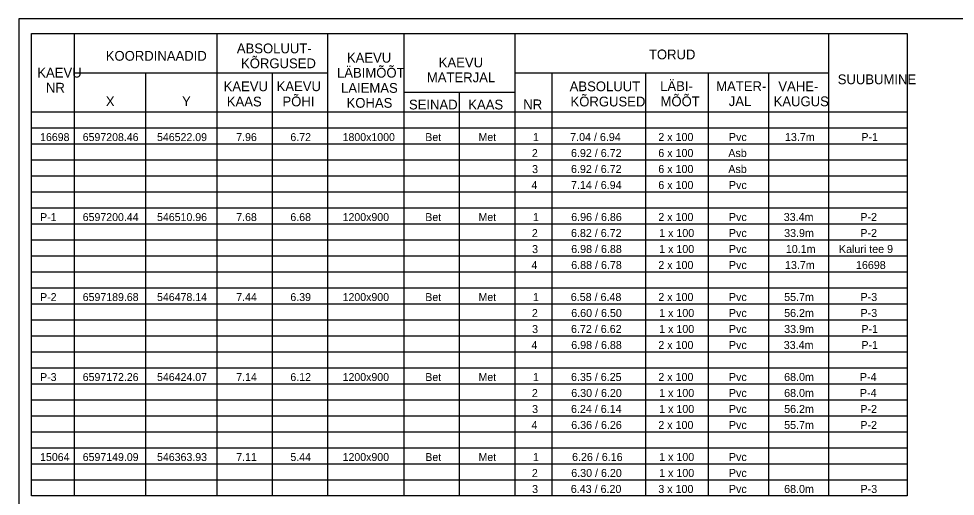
# Model space of a CAD drawing. Extents: x 546339 to 546593, y 6597108 to 6597251.
# Drawn here: x 546339.4 to 546434.2, y 6597202.4 to 6597250.7 of the extents above; entities that cross this region are included whole.
import ezdxf

# ---------------------------------------------------------------- set-up
doc = ezdxf.new("R2010")
doc.units = 0
doc.layers.add('ABIJOONIS', color=7, linetype='Continuous')
doc.layers.add('VORMISTUS', color=7, linetype='Continuous')

msp = doc.modelspace()

# ---------------------------------------------------------------- linework, layer by layer
at = {"layer": 'ABIJOONIS'}
msp.add_lwpolyline([(546340.681, 6597249.216), (546429.304, 6597249.216), (546429.304, 6597202.416), (546340.681, 6597202.416)], close=True, dxfattribs=at)
for points in [[(546344.997, 6597249.216), (546344.997, 6597202.416)], [(546359.423, 6597249.216), (546359.423, 6597202.416)], [(546370.643, 6597249.216), (546370.643, 6597202.416)], [(546378.364, 6597249.216), (546378.364, 6597202.416)], [(546389.584, 6597249.216), (546389.584, 6597202.416)], [(546421.342, 6597249.216), (546421.342, 6597202.416)], [(546344.997, 6597245.256), (546370.643, 6597245.256)], [(546352.21, 6597245.256), (546352.21, 6597202.416)], [(546365.033, 6597245.256), (546365.033, 6597202.416)], [(546389.584, 6597245.256), (546421.342, 6597245.256)], [(546393.324, 6597245.256), (546393.324, 6597202.416)], [(546402.828, 6597245.256), (546402.828, 6597202.416)], [(546409.173, 6597245.256), (546409.173, 6597202.416)], [(546415.257, 6597245.256), (546415.257, 6597202.416)], [(546378.364, 6597243.276), (546389.584, 6597243.276)], [(546383.974, 6597243.276), (546383.974, 6597202.416)], [(546340.681, 6597241.296), (546429.304, 6597241.296)], [(546340.681, 6597239.676), (546429.304, 6597239.676)], [(546340.681, 6597238.056), (546429.304, 6597238.056)], [(546340.681, 6597236.436), (546429.304, 6597236.436)], [(546340.681, 6597234.816), (546429.305, 6597234.816)], [(546340.681, 6597233.196), (546429.305, 6597233.196)], [(546340.681, 6597231.576), (546429.305, 6597231.576)], [(546340.681, 6597229.956), (546429.305, 6597229.956)], [(546340.681, 6597228.336), (546429.305, 6597228.336)], [(546340.681, 6597226.716), (546429.305, 6597226.716)], [(546340.681, 6597225.096), (546429.305, 6597225.096)], [(546340.681, 6597223.476), (546429.305, 6597223.476)], [(546340.682, 6597221.856), (546429.305, 6597221.856)], [(546340.682, 6597220.236), (546429.305, 6597220.236)], [(546340.682, 6597218.616), (546429.305, 6597218.616)], [(546340.682, 6597216.996), (546429.305, 6597216.996)], [(546340.682, 6597215.377), (546429.305, 6597215.376)], [(546340.682, 6597213.757), (546429.305, 6597213.756)], [(546340.682, 6597212.137), (546429.306, 6597212.136)], [(546340.682, 6597210.517), (546429.306, 6597210.516)], [(546340.682, 6597208.897), (546429.306, 6597208.896)], [(546340.682, 6597207.277), (546429.306, 6597207.276)], [(546340.682, 6597205.657), (546429.306, 6597205.656)], [(546340.682, 6597204.037), (546429.306, 6597204.036)]]:
    msp.add_lwpolyline(points, dxfattribs=at)
at = {"layer": 'VORMISTUS'}
msp.add_lwpolyline([(546593.177, 6597250.72), (546339.379, 6597250.72), (546339.379, 6597108.37), (546593.177, 6597108.37)], close=True, dxfattribs=at)

# ---------------------------------------------------------------- texts
at = {"layer": 'ABIJOONIS'}
for s, height, p in [('ABSOLUUT-', 0.99, (546361.456, 6597247.221)), ('TORUD', 0.99, (546403.167, 6597246.609)), ('KOORDINAADID', 0.98998, (546348.189, 6597246.465)), ('KÕRGUSED', 0.99, (546361.881, 6597245.709)), ('KAEVU', 0.99, (546372.599, 6597246.276)), ('KAEVU', 0.99, (546381.893, 6597245.799)), ('KAEVU', 0.99, (546341.256, 6597244.764)), ('LÄBIMÕÕT', 0.99, (546371.595, 6597244.755)), ('MATERJAL', 0.99, (546380.692, 6597244.287)), ('SUUBUMINE', 0.99, (546422.279, 6597244.087)), ('NR', 0.99, (546342.135, 6597243.243)), ('KAEVU', 0.99, (546360.117, 6597243.378)), ('KAEVU', 0.99, (546365.484, 6597243.387)), ('LAIEMAS', 0.99, (546372.005, 6597243.216)), ('ABSOLUUT', 0.99, (546395.145, 6597243.378)), ('LÄBI-', 0.99, (546404.304, 6597243.405)), ('MATER-', 0.99, (546409.975, 6597243.387)), ('VAHE-', 0.99, (546416.268, 6597243.378)), ('PÕHI', 0.99, (546366.074, 6597241.848)), ('KÕRGUSED', 0.99, (546395.232, 6597241.839)), ('MÕÕT', 0.99, (546404.343, 6597241.857)), ('X', 0.99, (546348.197, 6597241.866)), ('Y', 0.99, (546355.911, 6597241.875)), ('KAAS', 0.99, (546360.441, 6597241.839)), ('KOHAS', 0.99, (546372.562, 6597241.704)), ('SEINAD', 0.99, (546378.878, 6597241.533)), ('KAAS', 0.99, (546384.882, 6597241.533)), ('NR', 0.99, (546390.452, 6597241.551)), ('JAL', 0.99, (546411.247, 6597241.875)), ('KAUGUS', 0.99, (546415.788, 6597241.857)), ('1', 0.81, (546391.424, 6597238.326)), ('7.04 / 6.94', 0.81, (546395.197, 6597238.335)), ('2 x 100', 0.81, (546404.117, 6597238.335)), ('Pvc', 0.81, (546411.266, 6597238.335)), ('13.7m', 0.81, (546416.939, 6597238.335)), ('P-1', 0.81, (546424.671, 6597238.335)), ('2', 0.81, (546391.319, 6597236.706)), ('6.92 / 6.72', 0.81, (546395.281, 6597236.715)), ('6 x 100', 0.81, (546404.117, 6597236.715)), ('Asb', 0.81, (546411.203, 6597236.715)), ('3', 0.81, (546391.34, 6597235.086)), ('6.92 / 6.72', 0.81, (546395.281, 6597235.095)), ('6 x 100', 0.81, (546404.117, 6597235.095)), ('Asb', 0.81, (546411.203, 6597235.095)), ('4', 0.81, (546391.277, 6597233.466)), ('7.14 / 6.94', 0.81, (546395.281, 6597233.475)), ('6 x 100', 0.81, (546404.117, 6597233.475)), ('Pvc', 0.81, (546411.266, 6597233.475)), ('1', 0.81, (546391.424, 6597230.226)), ('6.96 / 6.86', 0.81, (546395.302, 6597230.235)), ('2 x 100', 0.81, (546404.117, 6597230.235)), ('Pvc', 0.81, (546411.266, 6597230.235)), ('33.4m', 0.81, (546416.814, 6597230.235)), ('P-2', 0.81, (546424.566, 6597230.235)), ('2', 0.81, (546391.319, 6597228.606)), ('6.82 / 6.72', 0.81, (546395.281, 6597228.615)), ('1 x 100', 0.81, (546404.202, 6597228.615)), ('Pvc', 0.81, (546411.266, 6597228.615)), ('33.9m', 0.81, (546416.856, 6597228.615)), ('P-2', 0.81, (546424.566, 6597228.615)), ('3', 0.81, (546391.34, 6597226.986)), ('6.98 / 6.88', 0.81, (546395.302, 6597226.995)), ('1 x 100', 0.81, (546404.202, 6597226.995)), ('Pvc', 0.81, (546411.266, 6597226.995)), ('10.1m', 0.81, (546417.024, 6597226.995)), ('Kaluri tee 9', 0.81, (546422.4, 6597226.995)), ('4', 0.81, (546391.277, 6597225.366)), ('6.88 / 6.78', 0.81, (546395.302, 6597225.375)), ('2 x 100', 0.81, (546404.117, 6597225.375)), ('Pvc', 0.81, (546411.266, 6597225.375)), ('13.7m', 0.81, (546416.94, 6597225.375)), ('16698', 0.81, (546424.125, 6597225.375)), ('6.58 / 6.48', 0.81, (546395.261, 6597222.135)), ('1', 0.81, (546391.425, 6597222.126)), ('2 x 100', 0.81, (546404.118, 6597222.135)), ('Pvc', 0.81, (546411.267, 6597222.135)), ('55.7m', 0.81, (546416.856, 6597222.135)), ('P-3', 0.81, (546424.588, 6597222.135)), ('2', 0.81, (546391.32, 6597220.506)), ('6.60 / 6.50', 0.81, (546395.303, 6597220.515)), ('1 x 100', 0.81, (546404.202, 6597220.515)), ('Pvc', 0.81, (546411.267, 6597220.515)), ('56.2m', 0.81, (546416.856, 6597220.515)), ('P-3', 0.81, (546424.588, 6597220.515)), ('3', 0.81, (546391.341, 6597218.886)), ('6.72 / 6.62', 0.81, (546395.282, 6597218.895)), ('1 x 100', 0.81, (546404.202, 6597218.895)), ('Pvc', 0.81, (546411.267, 6597218.895)), ('33.9m', 0.81, (546416.856, 6597218.895)), ('P-1', 0.81, (546424.672, 6597218.895)), ('4', 0.81, (546391.277, 6597217.266)), ('6.98 / 6.88', 0.81, (546395.303, 6597217.275)), ('2 x 100', 0.81, (546404.118, 6597217.275)), ('Pvc', 0.81, (546411.267, 6597217.275)), ('33.4m', 0.81, (546416.814, 6597217.275)), ('P-1', 0.81, (546424.672, 6597217.275)), ('1', 0.81, (546391.425, 6597214.026)), ('6.35 / 6.25', 0.81, (546395.282, 6597214.035)), ('2 x 100', 0.81, (546404.118, 6597214.035)), ('Pvc', 0.81, (546411.267, 6597214.035)), ('68.0m', 0.81, (546416.856, 6597214.035)), ('P-4', 0.81, (546424.525, 6597214.035)), ('2', 0.81, (546391.32, 6597212.406)), ('6.30 / 6.20', 0.81, (546395.303, 6597212.415)), ('1 x 100', 0.81, (546404.202, 6597212.415)), ('Pvc', 0.81, (546411.267, 6597212.415)), ('68.0m', 0.81, (546416.856, 6597212.415)), ('P-4', 0.81, (546424.525, 6597212.415)), ('3', 0.81, (546391.341, 6597210.786)), ('6.24 / 6.14', 0.81, (546395.282, 6597210.795)), ('1 x 100', 0.81, (546404.202, 6597210.795)), ('Pvc', 0.81, (546411.267, 6597210.795)), ('56.2m', 0.81, (546416.856, 6597210.795)), ('P-2', 0.81, (546424.567, 6597210.795)), ('4', 0.81, (546391.278, 6597209.166)), ('6.36 / 6.26', 0.81, (546395.303, 6597209.175)), ('2 x 100', 0.81, (546404.118, 6597209.175)), ('Pvc', 0.81, (546411.267, 6597209.175)), ('55.7m', 0.81, (546416.856, 6597209.175)), ('P-2', 0.81, (546424.567, 6597209.175)), ('1', 0.81, (546391.425, 6597205.926)), ('6.26 / 6.16', 0.81, (546395.387, 6597205.935)), ('1 x 100', 0.81, (546404.202, 6597205.935)), ('Pvc', 0.81, (546411.267, 6597205.935)), ('2', 0.81, (546391.32, 6597204.306)), ('6.30 / 6.20', 0.81, (546395.303, 6597204.315)), ('1 x 100', 0.81, (546404.202, 6597204.315)), ('Pvc', 0.81, (546411.267, 6597204.315)), ('3', 0.81, (546391.341, 6597202.686)), ('6.43 / 6.20', 0.81, (546395.261, 6597202.695)), ('3 x 100', 0.81, (546404.118, 6597202.695)), ('Pvc', 0.81, (546411.267, 6597202.695)), ('68.0m', 0.81, (546416.856, 6597202.695)), ('P-3', 0.81, (546424.588, 6597202.695))]:
    msp.add_text(s, height=height, rotation=359.99998, dxfattribs=at).set_placement(p)
for s, p in [('16698', (546341.54, 6597238.331)), ('6597208.46', (546345.856, 6597238.331)), ('546522.09', (546353.379, 6597238.331)), ('7.96', (546361.396, 6597238.331)), ('6.72', (546366.878, 6597238.331)), ('1800x1000', (546372.162, 6597238.331)), ('Bet', (546380.533, 6597238.331)), ('Met', (546385.921, 6597238.331)), ('P-1', (546341.541, 6597230.231)), ('6597200.44', (546345.857, 6597230.231)), ('546510.96', (546353.38, 6597230.231)), ('7.68', (546361.397, 6597230.231)), ('6.68', (546366.878, 6597230.231)), ('1200x900', (546372.163, 6597230.231)), ('Bet', (546380.533, 6597230.231)), ('Met', (546385.921, 6597230.231)), ('P-2', (546341.541, 6597222.131)), ('6597189.68', (546345.857, 6597222.131)), ('546478.14', (546353.38, 6597222.131)), ('7.44', (546361.397, 6597222.131)), ('6.39', (546366.878, 6597222.131)), ('1200x900', (546372.163, 6597222.131)), ('Bet', (546380.533, 6597222.131)), ('Met', (546385.922, 6597222.131)), ('P-3', (546341.541, 6597214.031)), ('6597172.26', (546345.857, 6597214.031)), ('546424.07', (546353.38, 6597214.031)), ('7.14', (546361.397, 6597214.031)), ('6.12', (546366.878, 6597214.031)), ('1200x900', (546372.163, 6597214.031)), ('Bet', (546380.533, 6597214.031)), ('Met', (546385.922, 6597214.031)), ('15064', (546341.541, 6597205.931)), ('6597149.09', (546345.857, 6597205.931)), ('546363.93', (546353.38, 6597205.931)), ('7.11', (546361.397, 6597205.931)), ('5.44', (546366.879, 6597205.931)), ('1200x900', (546372.164, 6597205.931)), ('Bet', (546380.534, 6597205.931)), ('Met', (546385.922, 6597205.931))]:
    msp.add_text(s, height=0.8, dxfattribs=at).set_placement(p)

doc.saveas('drawing.dxf')
